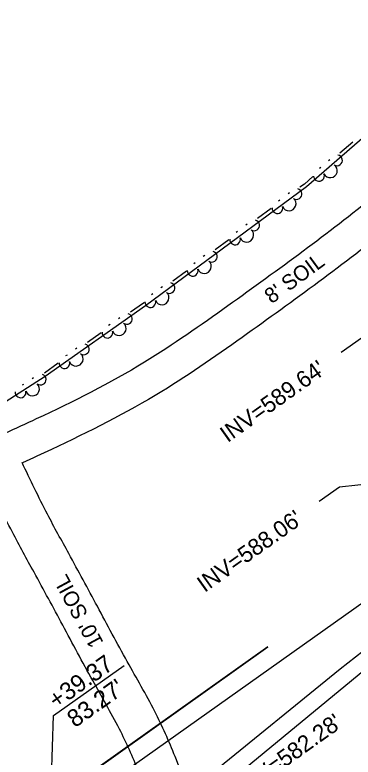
# Model space of a CAD drawing. Extents: x 1577032 to 1581865, y 611492 to 615011.
# Drawn here: x 1580707.1 to 1580788.7, y 614069.3 to 614248.5 of the extents above; entities that cross this region are included whole.
import ezdxf

# ---------------------------------------------------------------- set-up
doc = ezdxf.new("R2010")
doc.units = 0
for name, color, linetype in [('Exist Other Culture Fence Line', 7, 'Continuous'), ('Exist Property Tie Line Leader', 7, 'Continuous'), ('Exist Property Tie Line Text', 7, 'Continuous'), ('Exist Right of Way Line', 7, 'Continuous'), ('Exist Structure Minor Pipes CMP 18 Inch Invert', 7, 'Continuous'), ('Exist Structure Minor Pipes CMP 18 Inch Leader', 7, 'Continuous'), ('Exist Utilities Telephone UG FO SUE LOS B', 7, 'Continuous'), ('Exist Utilities Water UG Line SUE LOS B', 7, 'Continuous'), ('Old_Level_11', 7, 'Continuous'), ('Scratch_Level_4', 7, 'Continuous')]:
    doc.layers.add(name, color=color, linetype=linetype)

msp = doc.modelspace()

# ---------------------------------------------------------------- linework, layer by layer
at = {"layer": 'Exist Other Culture Fence Line'}
msp.add_line((1580768.114, 614096), (1580696.9270000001, 614045.292), dxfattribs=at)
for points in [[(1580768.114, 614096), (1580696.9270000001, 614045.292), (1580667.048, 614086.294)], [(1580667.048, 614086.294), (1580696.9270000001, 614045.292), (1580768.114, 614096)]]:
    msp.add_lwpolyline(points, dxfattribs=at)
at = {"layer": 'Exist Property Tie Line Leader'}
msp.add_lwpolyline([(1580714.4920501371, 614018.8793008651), (1580716.4645911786, 614079.3865123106), (1580733.5001176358, 614091.4840844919)], dxfattribs=at)
at = {"layer": 'Exist Right of Way Line'}
msp.add_lwpolyline([(1580350.48594625, 613793.9036433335), (1581560.2263262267, 614652.9854831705)], dxfattribs=at)
at = {"layer": 'Exist Structure Minor Pipes CMP 18 Inch Leader'}
for points in [[(1580801.861, 614164.2539999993), (1580790.708049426, 614170.5109281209), (1580785.8160698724, 614167.0369482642)], [(1580794.273, 614135.478), (1580785.413540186, 614134.5033615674), (1580780.5215606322, 614131.0293817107)]]:
    msp.add_lwpolyline(points, dxfattribs=at)
at = {"layer": 'Exist Utilities Telephone UG FO SUE LOS B'}
msp.add_lwpolyline([(1580541.919, 613911.3394), (1580565.994, 613928.4968), (1580575.3830000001, 613936.5393), (1580607.264, 613958.8003), (1580640.939, 613978.4368000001), (1580673.151, 613998.3057), (1580719.171, 614030.817), (1580788.349, 614087.8544), (1580845.174, 614134.9058), (1580876.014, 614149.9581), (1580927.925, 614187.5998), (1580984.724, 614225.9754), (1580987.351, 614228.7703), (1581072.57, 614287.7137), (1581106.013, 614311.085), (1581124.143, 614323.4137), (1581136.772, 614334.4010000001), (1581140.556, 614340.6799), (1581160.3530000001, 614356.311), (1581239.563, 614412.2149)], dxfattribs=at)
at = {"layer": 'Exist Utilities Water UG Line SUE LOS B'}
for p, q in [((1580785.601, 614090.6692), (1580843.741, 614136.3588)), ((1580716.3830000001, 614034.482), (1580785.601, 614090.6692))]:
    msp.add_line(p, q, dxfattribs=at)
at = {"layer": 'Old_Level_11'}
for points in [[(1580805.2315918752, 614231.2059183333), (1580793.3238072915, 614220.75482375), (1580777.4601579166, 614207.0548839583), (1580738.5995072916, 614178.3008404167), (1580714.44191125, 614161.1945754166), (1580695.2596989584, 614148.985774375), (1580670.7485931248, 614138.7044629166), (1580645.9783014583, 614126.0888385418), (1580618.9319316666, 614113.0614695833), (1580597.4588775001, 614101.5375425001), (1580588.5022025, 614095.9904735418), (1580578.6933310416, 614091.0273929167), (1580573.7778225, 614091.3800825), (1580567.6377429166, 614100.9338691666), (1580576.7322129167, 614123.218109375), (1580588.5989870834, 614152.0410504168), (1580595.7708887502, 614169.5442962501), (1580610.6806358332, 614194.9026772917)], [(1580788.6387772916, 614217.7930514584), (1580785.5351089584, 614215.112610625)], [(1580783.0949891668, 614213.5468329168), (1580782.7841302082, 614213.2786247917)], [(1580780.9238977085, 614211.6710164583), (1580780.61303875, 614211.4036285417)], [(1580779.0169133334, 614209.4835208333), (1580776.9475277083, 614207.6954666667), (1580775.89848125, 614206.9195495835)], [(1580773.3468131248, 614205.5415995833), (1580773.017089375, 614205.2971775)], [(1580771.038746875, 614203.8339258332), (1580770.709023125, 614203.5895037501)], [(1580768.9751027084, 614201.7973485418), (1580765.6786854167, 614199.3580489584)], [(1580763.1286577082, 614197.9800989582), (1580762.7989339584, 614197.7364970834)], [(1580760.8205914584, 614196.2724252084), (1580760.4908677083, 614196.0288233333)], [(1580758.755306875, 614194.2358479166), (1580755.4588895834, 614191.7965483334)], [(1580752.9072214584, 614190.417778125), (1580752.5774977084, 614190.1733560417)], [(1580750.5991552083, 614188.7101043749), (1580750.2694314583, 614188.4656822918)], [(1580748.5355110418, 614186.6735270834), (1580745.23909375, 614184.2342274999)], [(1580742.6890660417, 614182.8562774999), (1580742.3593422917, 614182.6126756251)], [(1580740.3809997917, 614181.14860375), (1580740.0512760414, 614180.9050018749)], [(1580738.314895, 614179.1112062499), (1580738.1180450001, 614178.9652091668), (1580734.9864895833, 614176.7473658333)], [(1580732.4061141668, 614175.4227293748), (1580732.0714691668, 614175.1856891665)], [(1580730.0635991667, 614173.764268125), (1580729.7289541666, 614173.5272279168)], [(1580727.958124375, 614171.7703416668), (1580724.6108541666, 614169.3999395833)], [(1580722.0312989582, 614168.0761233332), (1580721.6966539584, 614167.8390831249)], [(1580719.68796375, 614166.4168418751), (1580719.35331875, 614166.1798016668)], [(1580717.5824889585, 614164.423735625), (1580714.23521875, 614162.0533335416)], [(1580711.6376189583, 614160.8673122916), (1580711.2914910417, 614160.6474964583)], [(1580709.21554375, 614159.3261408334), (1580708.8694158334, 614159.1063250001)]]:
    msp.add_lwpolyline(points, dxfattribs=at)
for centre, radius, start, end in [((1580784.829671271, 614213.4192385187), 1.2968632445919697, 239.24903055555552, 80.0456), ((1580783.1930981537, 614210.9221489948), 1.690902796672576, 206.77783611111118, 54.85032500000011), ((1580780.4843378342, 614209.6665833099), 1.2968632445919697, 181.58256111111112, 22.379130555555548), ((1580775.0678864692, 614205.2847777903), 1.2968632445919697, 234.93368611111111, 75.73025555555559), ((1580773.2480575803, 614202.9179126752), 1.690902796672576, 202.46249166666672, 50.53498055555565), ((1580770.4525005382, 614201.8697292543), 1.2968632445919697, 177.2672166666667, 18.0637861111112), ((1580764.8481033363, 614197.7228846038), 1.2968632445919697, 234.93368611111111, 75.73025555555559), ((1580763.0282744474, 614195.3560194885), 1.690902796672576, 202.46249166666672, 50.53498055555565), ((1580760.2327174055, 614194.3078360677), 1.2968632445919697, 177.2672166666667, 18.0637861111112), ((1580754.6283202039, 614190.1609914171), 1.2968632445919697, 234.93368611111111, 75.73025555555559), ((1580752.8084913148, 614187.794126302), 1.690902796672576, 202.46249166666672, 50.53498055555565), ((1580750.0129342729, 614186.7459428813), 1.2968632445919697, 177.2672166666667, 18.0637861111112), ((1580744.408537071, 614182.5990982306), 1.2968632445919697, 234.93368611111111, 75.73025555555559), ((1580742.588708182, 614180.2322331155), 1.690902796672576, 202.46249166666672, 50.53498055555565), ((1580739.79315114, 614179.1840496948), 1.2968632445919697, 177.2672166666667, 18.0637861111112), ((1580734.1215942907, 614175.1299799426), 1.2968632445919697, 233.7376888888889, 74.53425833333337), ((1580732.2527592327, 614172.8016150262), 1.6909027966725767, 201.2664944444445, 49.33898333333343), ((1580729.4359329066, 614171.8120105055), 1.2968632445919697, 176.0712194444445, 16.86778888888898), ((1580723.7462012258, 614167.7830476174), 1.2968632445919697, 233.7376888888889, 74.53425833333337), ((1580721.8773661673, 614165.4546827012), 1.6909027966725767, 201.2664944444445, 49.33898333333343), ((1580719.0605398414, 614164.4650781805), 1.2968632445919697, 176.0712194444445, 16.86778888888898), ((1580713.3346988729, 614160.4898738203), 1.2968632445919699, 230.9102638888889, 71.70683333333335), ((1580711.3532856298, 614158.2565289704), 1.690902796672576, 198.43906944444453, 46.511558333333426), ((1580708.491073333, 614157.4070771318), 1.2968632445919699, 173.24379444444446, 14.040363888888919)]:
    msp.add_arc(centre, radius, start, end, dxfattribs=at)
at = {"layer": 'Scratch_Level_4'}
for points in [[(1580810.2159979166, 614218.6468883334), (1580794.0103216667, 614204.93792625), (1580776.6301070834, 614191.4594427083), (1580758.5158060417, 614178.291818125), (1580738.3739500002, 614164.6845618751), (1580712.2855835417, 614150.9829816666), (1580696.9435866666, 614143.9160666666), (1580679.7019872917, 614135.5876712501), (1580659.1303420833, 614126.8385089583), (1580639.57985625, 614117.5947610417), (1580624.6848729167, 614110.0693495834), (1580609.6619370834, 614101.2004368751), (1580587.2923952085, 614087.3651627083), (1580579.9556316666, 614081.0093683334), (1580573.7425535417, 614079.4526129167), (1580566.2097602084, 614084.8889537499), (1580558.84675, 614093.5544547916), (1580547.5418185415, 614104.9906195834), (1580534.6227170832, 614117.2724191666), (1580522.9306472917, 614130.9575952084), (1580516.2032985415, 614138.4444568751)], [(1580815.637575, 614212.4895843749), (1580799.1743533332, 614198.5632670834), (1580781.555458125, 614184.9002366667), (1580763.2246220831, 614171.5743118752), (1580742.5898208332, 614157.6340510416), (1580715.9109043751, 614143.6224320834), (1580708.9555377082, 614140.4186983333)], [(1580750.5868520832, 614056.0594510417), (1580745.7623866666, 614069.4772391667), (1580740.8444175, 614080.3843695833), (1580734.2294372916, 614092.3963206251), (1580727.0075029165, 614105.747671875), (1580720.1070902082, 614118.4887881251), (1580714.9652041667, 614127.9876208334), (1580708.8333266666, 614140.4441247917)], [(1580741.545695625, 614053.0845554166), (1580736.9353045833, 614065.9068722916), (1580732.3273741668, 614076.1274883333), (1580725.8780760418, 614087.8376027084), (1580718.6397374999, 614101.2184814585), (1580711.740145, 614113.9587775), (1580706.5104966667, 614123.6200114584), (1580700.10631, 614136.6293358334)]]:
    msp.add_spline(points, degree=3, dxfattribs=at)

# ---------------------------------------------------------------- texts
at = {"layer": 'Exist Property Tie Line Text'}
for s, p in [('+39.37', (1580717.1255785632, 614080.8561762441)), ("83.27'", (1580721.605930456, 614076.3100267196))]:
    msp.add_text(s, height=4.2, rotation=35.33965074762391, dxfattribs=at).set_placement(p)
at = {"layer": 'Exist Structure Minor Pipes CMP 18 Inch Invert'}
for s, height, p in [("INV=589.64'", 3.999999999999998, (1580758.43109584, 614145.1368468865)), ("INV=588.06'", 3.999999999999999, (1580752.8797897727, 614108.9469191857)), ("INV=582.28'", 3.999999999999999, (1580762.4006928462, 614059.7959734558))]:
    msp.add_text(s, height=height, rotation=35.38000274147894, dxfattribs=at).set_placement(p)
at = {"layer": 'Scratch_Level_4'}
for s, rotation, p in [("8' SOIL", 36.291552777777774, (1580769.0432301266, 614178.6535416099)), ("10' SOIL", 118.42520277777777, (1580728.5866225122, 614097.0116368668))]:
    msp.add_text(s, height=3.6909375, rotation=rotation, dxfattribs=at).set_placement(p)

doc.saveas('drawing.dxf')
